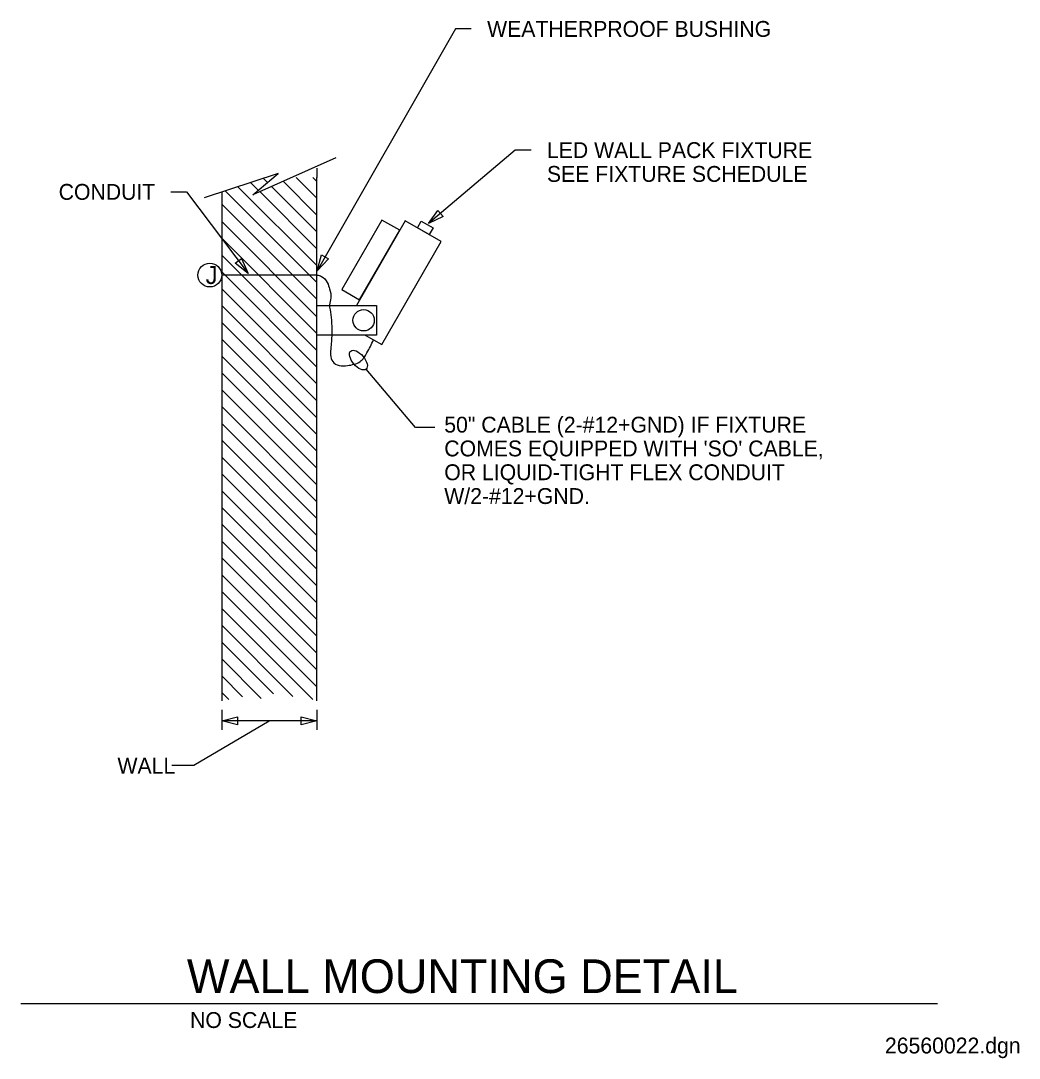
# Model space of a CAD drawing. Extents: x 10181.9 to 10223.9, y 10049.8 to 10093.4.
import ezdxf

# ---------------------------------------------------------------- set-up
doc = ezdxf.new("R2010")
doc.units = 0
for name, color, linetype in [('G-ANNO-TEXT', 7, 'Continuous'), ('G-DETL-LINE', 7, 'Continuous'), ('G-DETL-OTLN', 7, 'Continuous'), ('G-DETL-PATT', 7, 'Continuous')]:
    doc.layers.add(name, color=color, linetype=linetype)

msp = doc.modelspace()

# ---------------------------------------------------------------- linework, layer by layer
at = {"layer": 'G-ANNO-TEXT'}
for p, q in [((10200.194, 10093.039), (10194.382, 10082.875)), ((10200.86, 10093.039), (10200.194, 10093.039)), ((10202.708, 10087.944), (10199.059, 10084.854)), ((10203.374, 10087.944), (10202.708, 10087.944)), ((10188.232, 10086.189), (10188.899, 10086.189)), ((10188.899, 10086.189), (10191.482, 10082.763)), ((10198.511, 10076.287), (10196.442, 10078.736)), ((10199.327, 10076.287), (10198.511, 10076.287)), ((10190.374, 10064.42), (10190.374, 10063.583)), ((10194.374, 10064.42), (10194.374, 10063.583)), ((10189.207, 10062.096), (10192.374, 10063.958)), ((10190.374, 10063.958), (10190.374, 10063.958)), ((10194.374, 10063.958), (10190.374, 10063.958)), ((10188.277, 10062.096), (10189.207, 10062.096)), ((10181.93, 10052.082), (10220.455, 10052.082))]:
    msp.add_line(p, q, dxfattribs=at)
msp.add_lwpolyline([(10195.176, 10087.622), (10191.678, 10086.068), (10192.749, 10086.961), (10189.643, 10085.943)], dxfattribs=at)
for points in [[(10199.675, 10085.157), (10199.059, 10084.854), (10199.46, 10085.412)], [(10191.213, 10083.396), (10191.482, 10082.763), (10190.947, 10083.195)], [(10194.857, 10083.371), (10194.382, 10082.875), (10194.568, 10083.537)], [(10191.041, 10063.791), (10190.374, 10063.958), (10191.041, 10064.125)], [(10193.707, 10064.125), (10194.374, 10063.958), (10193.707, 10063.791)]]:
    msp.add_lwpolyline(points, close=True, dxfattribs=at)
msp.add_ellipse((10196.12, 10079.118), major_axis=(-0.323, 0.382), ratio=0.5, dxfattribs=at)
at = {"layer": 'G-DETL-LINE'}
for p, q in [((10194.374, 10087.193), (10194.374, 10086.795)), ((10194.374, 10064.795), (10194.374, 10086.795)), ((10190.374, 10086.183), (10190.374, 10064.795))]:
    msp.add_line(p, q, dxfattribs=at)
at = {"layer": 'G-DETL-OTLN'}
for p, q in [((10198.086, 10084.974), (10196.033, 10081.418)), ((10199.602, 10084.099), (10198.086, 10084.974)), ((10197.102, 10079.769), (10199.602, 10084.099)), ((10194.374, 10082.693), (10190.374, 10082.693)), ((10196.404, 10080.172), (10197.102, 10079.769))]:
    msp.add_line(p, q, dxfattribs=at)
for points in [[(10197.856, 10084.575), (10197.108, 10085.007), (10195.42, 10082.083), (10196.167, 10081.651)], [(10199.09, 10084.395), (10198.598, 10084.679), (10198.763, 10084.964), (10199.254, 10084.68)], [(10194.374, 10081.418), (10196.882, 10081.418), (10196.882, 10080.172), (10194.374, 10080.172)]]:
    msp.add_lwpolyline(points, close=True, dxfattribs=at)
for centre, radius in [((10189.874, 10082.693), 0.5), ((10196.336, 10080.795), 0.449)]:
    msp.add_circle(centre, radius, dxfattribs=at)
msp.add_spline([(10194.374, 10082.693), (10194.566, 10082.639), (10194.812, 10082.374), (10194.907, 10082.109), (10194.964, 10081.73), (10194.907, 10081.446), (10194.926, 10081.238), (10194.982, 10080.802), (10195.001, 10080.272), (10194.964, 10079.666), (10195.039, 10079.06), (10195.304, 10078.89), (10195.664, 10078.89), (10196.194, 10079.06), (10196.477, 10079.42), (10196.753, 10079.971)], degree=3, dxfattribs=at)
at = {"layer": 'G-DETL-PATT'}
for p, q in [((10191.058, 10086.407), (10194.374, 10083.091)), ((10191.591, 10086.582), (10191.91, 10086.262)), ((10192.124, 10086.756), (10192.296, 10086.584)), ((10192.463, 10086.417), (10194.366, 10084.514)), ((10192.952, 10086.634), (10194.374, 10085.213)), ((10193.499, 10086.795), (10194.374, 10085.92)), ((10194.206, 10086.795), (10194.374, 10086.627)), ((10190.526, 10086.233), (10194.374, 10082.384)), ((10191.973, 10086.199), (10194.374, 10083.799)), ((10190.374, 10085.677), (10194.374, 10081.677)), ((10190.391, 10084.926), (10194.374, 10080.944)), ((10190.374, 10084.237), (10194.374, 10080.237)), ((10190.374, 10083.529), (10194.374, 10079.529)), ((10190.374, 10082.822), (10194.374, 10078.822)), ((10190.374, 10082.115), (10194.374, 10078.115)), ((10190.374, 10081.408), (10194.374, 10077.408)), ((10190.374, 10080.701), (10194.35, 10076.725)), ((10190.374, 10079.994), (10194.374, 10075.994)), ((10190.374, 10079.287), (10194.374, 10075.287)), ((10190.374, 10078.58), (10194.374, 10074.58)), ((10190.374, 10077.873), (10194.374, 10073.873)), ((10190.374, 10077.166), (10194.374, 10073.166)), ((10190.374, 10076.458), (10194.374, 10072.458)), ((10190.374, 10075.751), (10194.374, 10071.751)), ((10190.374, 10075.044), (10194.374, 10071.044)), ((10190.374, 10074.337), (10194.374, 10070.337)), ((10190.374, 10073.63), (10194.374, 10069.63)), ((10190.374, 10072.923), (10194.374, 10068.923)), ((10190.374, 10072.216), (10194.374, 10068.216)), ((10190.374, 10071.509), (10194.374, 10067.509)), ((10190.374, 10070.802), (10194.374, 10066.802)), ((10190.374, 10070.095), (10194.374, 10066.095)), ((10190.374, 10069.387), (10194.374, 10065.387)), ((10190.374, 10068.68), (10194.203, 10064.852)), ((10190.374, 10067.973), (10193.362, 10064.985)), ((10190.374, 10067.266), (10192.544, 10065.096)), ((10190.374, 10066.559), (10192.037, 10064.896)), ((10190.374, 10065.852), (10191.254, 10064.972)), ((10190.374, 10065.145), (10190.668, 10064.851))]:
    msp.add_line(p, q, dxfattribs=at)

# ---------------------------------------------------------------- texts
at = {"layer": 'G-ANNO-TEXT'}
for s, height, p in [('WEATHERPROOF BUSHING', 0.66667, (10201.527, 10092.706)), ('LED WALL PACK FIXTURE', 0.66667, (10204.041, 10087.611)), ('SEE FIXTURE SCHEDULE', 0.66667, (10204.041, 10086.611)), ('CONDUIT', 0.6667, (10183.523, 10085.856)), ('50" CABLE (2-#12+GND) IF FIXTURE', 0.66667, (10199.727, 10076.072)), ("COMES EQUIPPED WITH 'SO' CABLE,", 0.66667, (10199.727, 10075.072)), ('OR LIQUID-TIGHT FLEX CONDUIT', 0.66667, (10199.727, 10074.072)), ('W/2-#12+GND.', 0.66667, (10199.727, 10073.072)), ('WALL', 0.6667, (10185.994, 10061.737)), ('WALL MOUNTING DETAIL', 1.41667, (10188.912, 10052.515)), ('NO SCALE', 0.6667, (10189.045, 10051.047)), ('26560022.dgn', 0.66667, (10218.244, 10049.976))]:
    msp.add_text(s, height=height, dxfattribs=at).set_placement(p)
at = {"layer": 'G-DETL-OTLN'}
msp.add_text('J', height=0.75, dxfattribs=at).set_placement((10189.699, 10082.318))

doc.saveas('drawing.dxf')
